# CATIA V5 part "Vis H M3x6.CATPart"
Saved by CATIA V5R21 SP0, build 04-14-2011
Part number: Vis H M3x6
Material "Acier": density 7860 kg/m3, Young's modulus 2e+11 Pa, Poisson ratio 0.266, thermal expansion 1.17e-05 1/K
Bounding box of the stored display mesh (mm): x -2.5 to 2.5, y -2.887 to 2.887, z 0 to 8
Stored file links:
  C:\Users\Utilisateur\Desktop\Fichiers à télécharger dans l'ouvrage\Exercice 9 Pompe de ventilation.CATDrawing (corrigé)\Vis H M3x6.CATPart
  C:\Program Files\Dassault Systemes\B21\win_b64\startup\materials\French\Catalog.CATMaterial
  C:\Users\Utilisateur\Desktop\Fichiers à télécharger dans l'ouvrage\Exercice 9 Pompe de ventilation.CATDrawing (corrigé)\CATIA_EnvironmentMap_Satin_512x512.jpg
  C:\Users\Olivier\Desktop\redaction CATIA (local)\pompe à moteur de ventilation refait\Pompe_a_moteur_de_ventilation.CATProduct
  C:\Users\Olivier\Desktop\redaction CATIA (local)\pompe à moteur de ventilation refait\Ecrou a collerette M5.CATPart
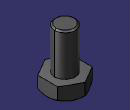
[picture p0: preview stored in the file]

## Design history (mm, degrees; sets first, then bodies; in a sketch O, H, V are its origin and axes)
Body1 (main body), material "Acier"
  Sketch1 on xy-plane, origin (0, 0, 0), H (1, 0, 0), V (0, 1, 0)
    circle A1 centre (0, 0) radius 1.5
    point P1 (2.5, -1.4434)
    point P2 (2.5, 1.4434)
    point P3 (0, 2.8868)
    point P4 (-2.5, 1.4434)
    point P5 (-2.5, -1.4434)
    point P6 (0, -2.8868)
    point P7 (2.5, 0)
    line L1 (2.5, -1.4434) -> (2.5, 1.4434)
    line L2 (2.5, 1.4434) -> (0, 2.8868)
    line L3 (0, 2.8868) -> (-2.5, 1.4434)
    line L4 (-2.5, 1.4434) -> (-2.5, -1.4434)
    line L5 (-2.5, -1.4434) -> (0, -2.8868)
    line L6 (0, -2.8868) -> (2.5, -1.4434)
    construction line L7 (0, 0) -> (2.5, 0)
    construction circle A2 centre (0, 0) radius 2.8868
    construction arc A3 centre (-2.5, -1.4434) radius 2.8868 from (-2.5, 1.4434) to (0, -2.8868) cw
    construction arc A4 centre (2.5, 1.4434) radius 2.8868 from (0, 2.8868) to (2.5, -1.4434) ccw
    distance L1 L4 = 5
    horizontal: L7 H
    coincidence: A2 P1, A2 P2, A2 P3, A2 P4, A2 P5, A2 P6, A3 O, A4 O
    midpoint: P7 L1
  MultiPad1: profile Sketch1, domains (length 2; length 8)
  Sketch2 on yz-plane, origin (0, 0, 0), H (0, 1, 0), V (0, 0, 1)
    line L1 (2.509, 0) -> (2.9319, 0.3605)
    point P1 (2.509, 0)
    line L2 (2.9319, 0.3605) -> (2.9319, 0)
    point P3 (2.9319, 0)
    line L3 (2.9319, 0) -> (2.509, 0)
    coincidence: P1 H, P3 H
    vertical: L2 V
    horizontal: L3 H
  Groove1: profile Sketch2, axis Sketch2.V, angle 360
  Chamfer1: length 0.2, angle 45, on face of MultiPad1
